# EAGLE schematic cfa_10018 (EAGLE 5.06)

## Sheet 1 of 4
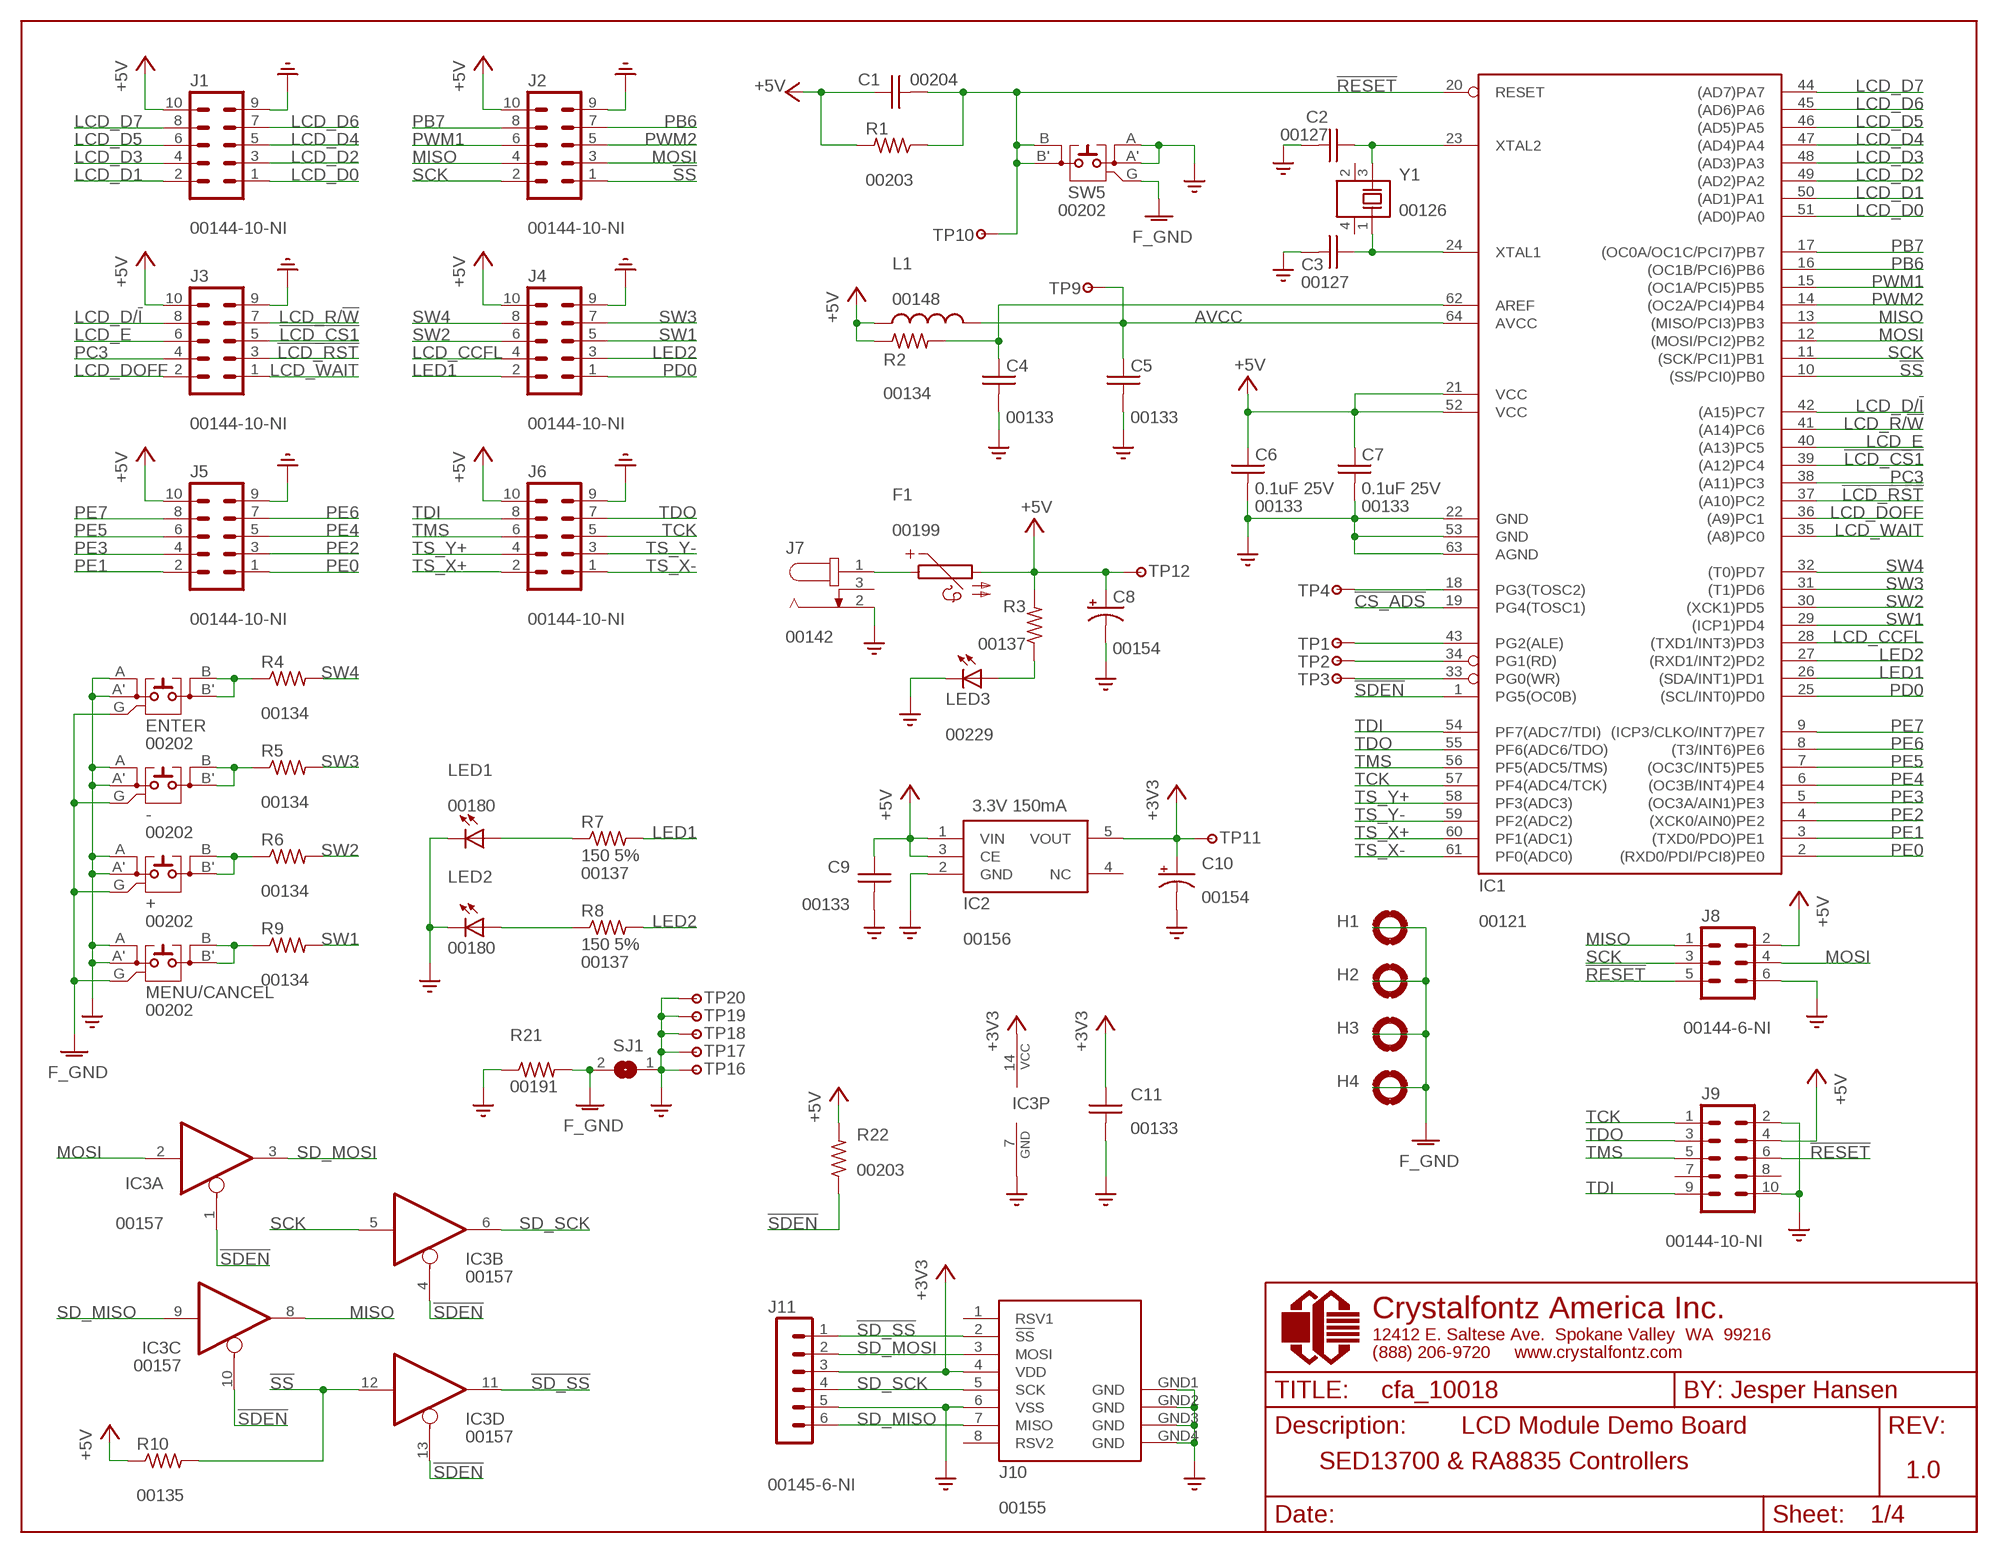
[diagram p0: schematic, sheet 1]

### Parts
+  00202  [EVQPB]
-  00202  [EVQPB]
C1  00204  [CAPC1608X90N]
C2  00127  [CAPC1608X87N]
C3  00127  [CAPC1608X87N]
C4  00133  [CAPC1608X87N]
C5  00133  [CAPC1608X87N]
C6  00133  [CAPC1608X87N]
C7  00133  [CAPC1608X87N]
C8  00154  [CAPMP6032X250N]
C9  00133  [CAPC1608X87N]
C10  00154  [CAPMP6032X250N]
C11  00133  [CAPC1608X87N]
ENTER  00202  [EVQPB]
F1  00199  [RESC3216X85N]
H1  MOUNT-PAD-ROUND3.2  [3,2-PAD]
H2  MOUNT-PAD-ROUND3.2  [3,2-PAD]
H3  MOUNT-PAD-ROUND3.2  [3,2-PAD]
H4  MOUNT-PAD-ROUND3.2  [3,2-PAD]
IC1  00121  [TQFP64-AEB]
IC2  00156  [SOT23-5L]
IC3  00157  [TSSOP14]
J1  00144-10-NI  [MA05-2]
J2  00144-10-NI  [MA05-2]
J3  00144-10-NI  [MA05-2]
J4  00144-10-NI  [MA05-2]
J5  00144-10-NI  [MA05-2]
J6  00144-10-NI  [MA05-2]
J7  00142  [PJ-102AH]
J8  00144-6-NI  [MA03-2]
J9  00144-10-NI  [MA05-2]
J10  00155  [3M_MICROSD]
J11  00145-6-NI  [MA06-1]
L1  00148  [R0805]
LED1  00180  [T776_LED_BOTTOM]
LED2  00180  [T776_LED_BOTTOM]
LED3  00229  [T776_LED_BOTTOM]
MENU/CANCEL  00202  [EVQPB]
R1  00203  [RESC1608X50N]
R2  00134  [RESC1608X38N]
R3  00137  [R0603]
R4  00134  [RESC1608X38N]
R5  00134  [RESC1608X38N]
R6  00134  [RESC1608X38N]
R7  00137  [R0603]
R8  00137  [R0603]
R9  00134  [RESC1608X38N]
R10  00135  [RESC1608X38N]
R21  00191  [RESC1608X55N]
R22  00203  [RESC1608X50N]
SJ1  SJ  [SJ]
SW5  00202  [EVQPB]
TP1  TP-VIA-3.2MM  [VIA-3.2MM-HOLE]
TP2  TP-VIA-3.2MM  [VIA-3.2MM-HOLE]
TP3  TP-VIA-3.2MM  [VIA-3.2MM-HOLE]
TP4  TP-VIA-3.2MM  [VIA-3.2MM-HOLE]
TP9  TP-VIA-1.0MM  [VIA-1MM-HOLE]
TP10  TP-VIA-1.0MM  [VIA-1MM-HOLE]
TP11  TP-VIA-1.0MM  [VIA-1MM-HOLE]
TP12  TP-VIA-1.0MM  [VIA-1MM-HOLE]
TP16  TP-VIA-1.0MM  [VIA-1MM-HOLE]
TP17  TP-VIA-1.0MM  [VIA-1MM-HOLE]
TP18  TP-VIA-1.0MM  [VIA-1MM-HOLE]
TP19  TP-VIA-1.0MM  [VIA-1MM-HOLE]
TP20  TP-VIA-1.0MM  [VIA-1MM-HOLE]
Y1  00126  [ECX-64]

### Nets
!CS_ADS: IC1.19(PG4(TOSC1)) ; also sheet 2
!LCD_CS1: IC1.39((A12)PC4) J3.5 ; also sheet 2
!LCD_RST: IC1.37((A10)PC2) J3.3 ; also sheet 2
!RESET: C1.2 IC1.20(RESET) J8.5 J9.6 R1.1 SW5.B SW5.B' TP10.1
!SD_SS: IC3.11(D:O) J10.2(!SS) J11.1
!SDEN: IC1.1(PG5(OC0B)) IC3.1(A:OE) IC3.4(B:OE) IC3.10(C:OE) IC3.13(D:OE) R22.1
!SS: IC1.10((SS/PCI0)PB0) IC3.12(D:I) J2.1 R10.2
+3V3: C10.1(+) C11.1 IC2.5(VOUT) IC3.14(P:VCC) J10.4(VDD) J11.3 TP11.1
+5V: C1.1 C6.1 C7.1 C8.1(+) C9.1 F1.2 IC1.21(VCC) IC1.52(VCC) IC2.1(VIN) IC2.3(CE) J1.10 J2.10 J3.10 J4.10 J5.10 J6.10 J8.2 J9.4 L1.1 R1.2 R2.1 R3.2 R10.1 R22.2 TP12.1 ; also sheet 2,3
AVCC: C5.1 IC1.64(AVCC) L1.2 TP9.1
FOO: +.A +.A' -.A -.A' C2.2 C3.2 C4.2 C5.2 C6.2 C7.2 C8.2(-) C9.2 C10.2(-) C11.2 ENTER.A ENTER.A' IC1.22(GND) IC1.53(GND) IC1.63(AGND) IC2.2(GND) IC3.7(P:GND) J1.9 J2.9 J3.9 J4.9 J5.9 J6.9 J7.2 J8.6 J9.2 J9.10 J10.6(VSS) J10.GND1(GND) J10.GND2(GND) J10.GND3(GND) J10.GND4(GND) J11.5 LED1.K(C) LED2.K(C) LED3.K(C) MENU/CANCEL.A MENU/CANCEL.A' R21.1 SJ1.1 SW5.A SW5.A' TP16.1 TP17.1 TP18.1 TP19.1 TP20.1 ; supply symbol labelled GND ; also sheet 2,3
GNDA: +.G -.G ENTER.G H1.B3,2(MOUNT) H2.B3,2(MOUNT) H3.B3,2(MOUNT) H4.B3,2(MOUNT) MENU/CANCEL.G R21.2 SJ1.2 SW5.G ; supply symbol labelled F_GND ; also sheet 2
LCD_CCFL: IC1.28((TXD1/INT3)PD3) J4.4 ; also sheet 3
LCD_D0: IC1.51((AD0)PA0) J1.1 ; also sheet 2
LCD_D1: IC1.50((AD1)PA1) J1.2 ; also sheet 2
LCD_D2: IC1.49((AD2)PA2) J1.3 ; also sheet 2
LCD_D3: IC1.48((AD3)PA3) J1.4 ; also sheet 2
LCD_D4: IC1.47((AD4)PA4) J1.5 ; also sheet 2
LCD_D5: IC1.46((AD5)PA5) J1.6 ; also sheet 2
LCD_D6: IC1.45((AD6)PA6) J1.7 ; also sheet 2
LCD_D7: IC1.44((AD7)PA7) J1.8 ; also sheet 2
LCD_D/!I: IC1.42((A15)PC7) J3.8 ; also sheet 2
LCD_DOFF: IC1.36((A9)PC1) J3.2 ; also sheet 2
LCD_E: IC1.40((A13)PC5) J3.6 ; also sheet 2
LCD_R/!W: IC1.41((A14)PC6) J3.7 ; also sheet 2
LCD_WAIT: IC1.35((A8)PC0) J3.1 ; also sheet 2
LED1: IC1.26((SDA/INT1)PD1) J4.2 R7.2
LED2: IC1.27((RXD1/INT2)PD2) J4.3 R8.2
MISO: IC1.13((MISO/PCI3)PB3) IC3.8(C:O) J2.4 J8.1 ; also sheet 2
MOSI: IC1.12((MOSI/PCI2)PB2) IC3.2(A:I) J2.3 J8.4 ; also sheet 2
N$1: C2.1 IC1.23(XTAL2) Y1.3
N$2: ENTER.B ENTER.B' R4.1
N$3: C3.1 IC1.24(XTAL1) Y1.1
N$4: -.B -.B' R5.1
N$6: +.B +.B' R6.1
N$7: LED1.A R7.1
N$8: MENU/CANCEL.B MENU/CANCEL.B' R9.1
N$9: C4.1 IC1.62(AREF) R2.2
N$10: LED2.A R8.1
N$11: IC1.43(PG2(ALE)) TP1.1
N$13: IC1.34(PG1(RD)) TP2.1
N$14: F1.1 J7.1
N$15: IC1.33(PG0(WR)) TP3.1
N$17: LED3.A R3.1
N$18: IC1.18(PG3(TOSC2)) TP4.1
PB6: IC1.16((OC1B/PCI6)PB6) J2.7
PB7: IC1.17((OC0A/OC1C/PCI7)PB7) J2.8
PC3: IC1.38((A11)PC3) J3.4
PD0: IC1.25((SCL/INT0)PD0) J4.1 ; also sheet 2
PE0: IC1.2((RXD0/PDI/PCI8)PE0) J5.1
PE1: IC1.3((TXD0/PDO)PE1) J5.2
PE2: IC1.4((XCK0/AIN0)PE2) J5.3
PE3: IC1.5((OC3A/AIN1)PE3) J5.4
PE4: IC1.6((OC3B/INT4)PE4) J5.5
PE5: IC1.7((OC3C/INT5)PE5) J5.6
PE6: IC1.8((T3/INT6)PE6) J5.7
PE7: IC1.9((ICP3/CLKO/INT7)PE7) J5.8
PWM1: IC1.15((OC1A/PCI5)PB5) J2.6 ; also sheet 3
PWM2: IC1.14((OC2A/PCI4)PB4) J2.5 ; also sheet 3
SCK: IC1.11((SCK/PCI1)PB1) IC3.5(B:I) J2.2 J8.3 ; also sheet 2
SD_MISO: IC3.9(C:I) J10.7(MISO) J11.6
SD_MOSI: IC3.3(A:O) J10.3(MOSI) J11.2
SD_SCK: IC3.6(B:O) J10.5(SCK) J11.4
SW1: IC1.29((ICP1)PD4) J4.5 R9.2
SW2: IC1.30((XCK1)PD5) J4.6 R6.2
SW3: IC1.31((T1)PD6) J4.7 R5.2
SW4: IC1.32((T0)PD7) J4.8 R4.2
TCK: IC1.57(PF4(ADC4/TCK)) J6.5 J9.1
TDI: IC1.54(PF7(ADC7/TDI)) J6.8 J9.9
TDO: IC1.55(PF6(ADC6/TDO)) J6.7 J9.3
TMS: IC1.56(PF5(ADC5/TMS)) J6.6 J9.5
TS_X+: IC1.60(PF1(ADC1)) J6.2 ; also sheet 2
TS_X-: IC1.61(PF0(ADC0)) J6.1 ; also sheet 2
TS_Y+: IC1.58(PF3(ADC3)) J6.4 ; also sheet 2
TS_Y-: IC1.59(PF2(ADC2)) J6.3 ; also sheet 2
Unconnected: IC2.4(NC) J7.3 J9.7 J9.8 J10.1(RSV1) J10.8(RSV2) Y1.2 Y1.4

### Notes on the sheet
- 3.3V 150mA
- LCD Module Demo Board
- SED13700 & RA8835 Controllers
- 1.0

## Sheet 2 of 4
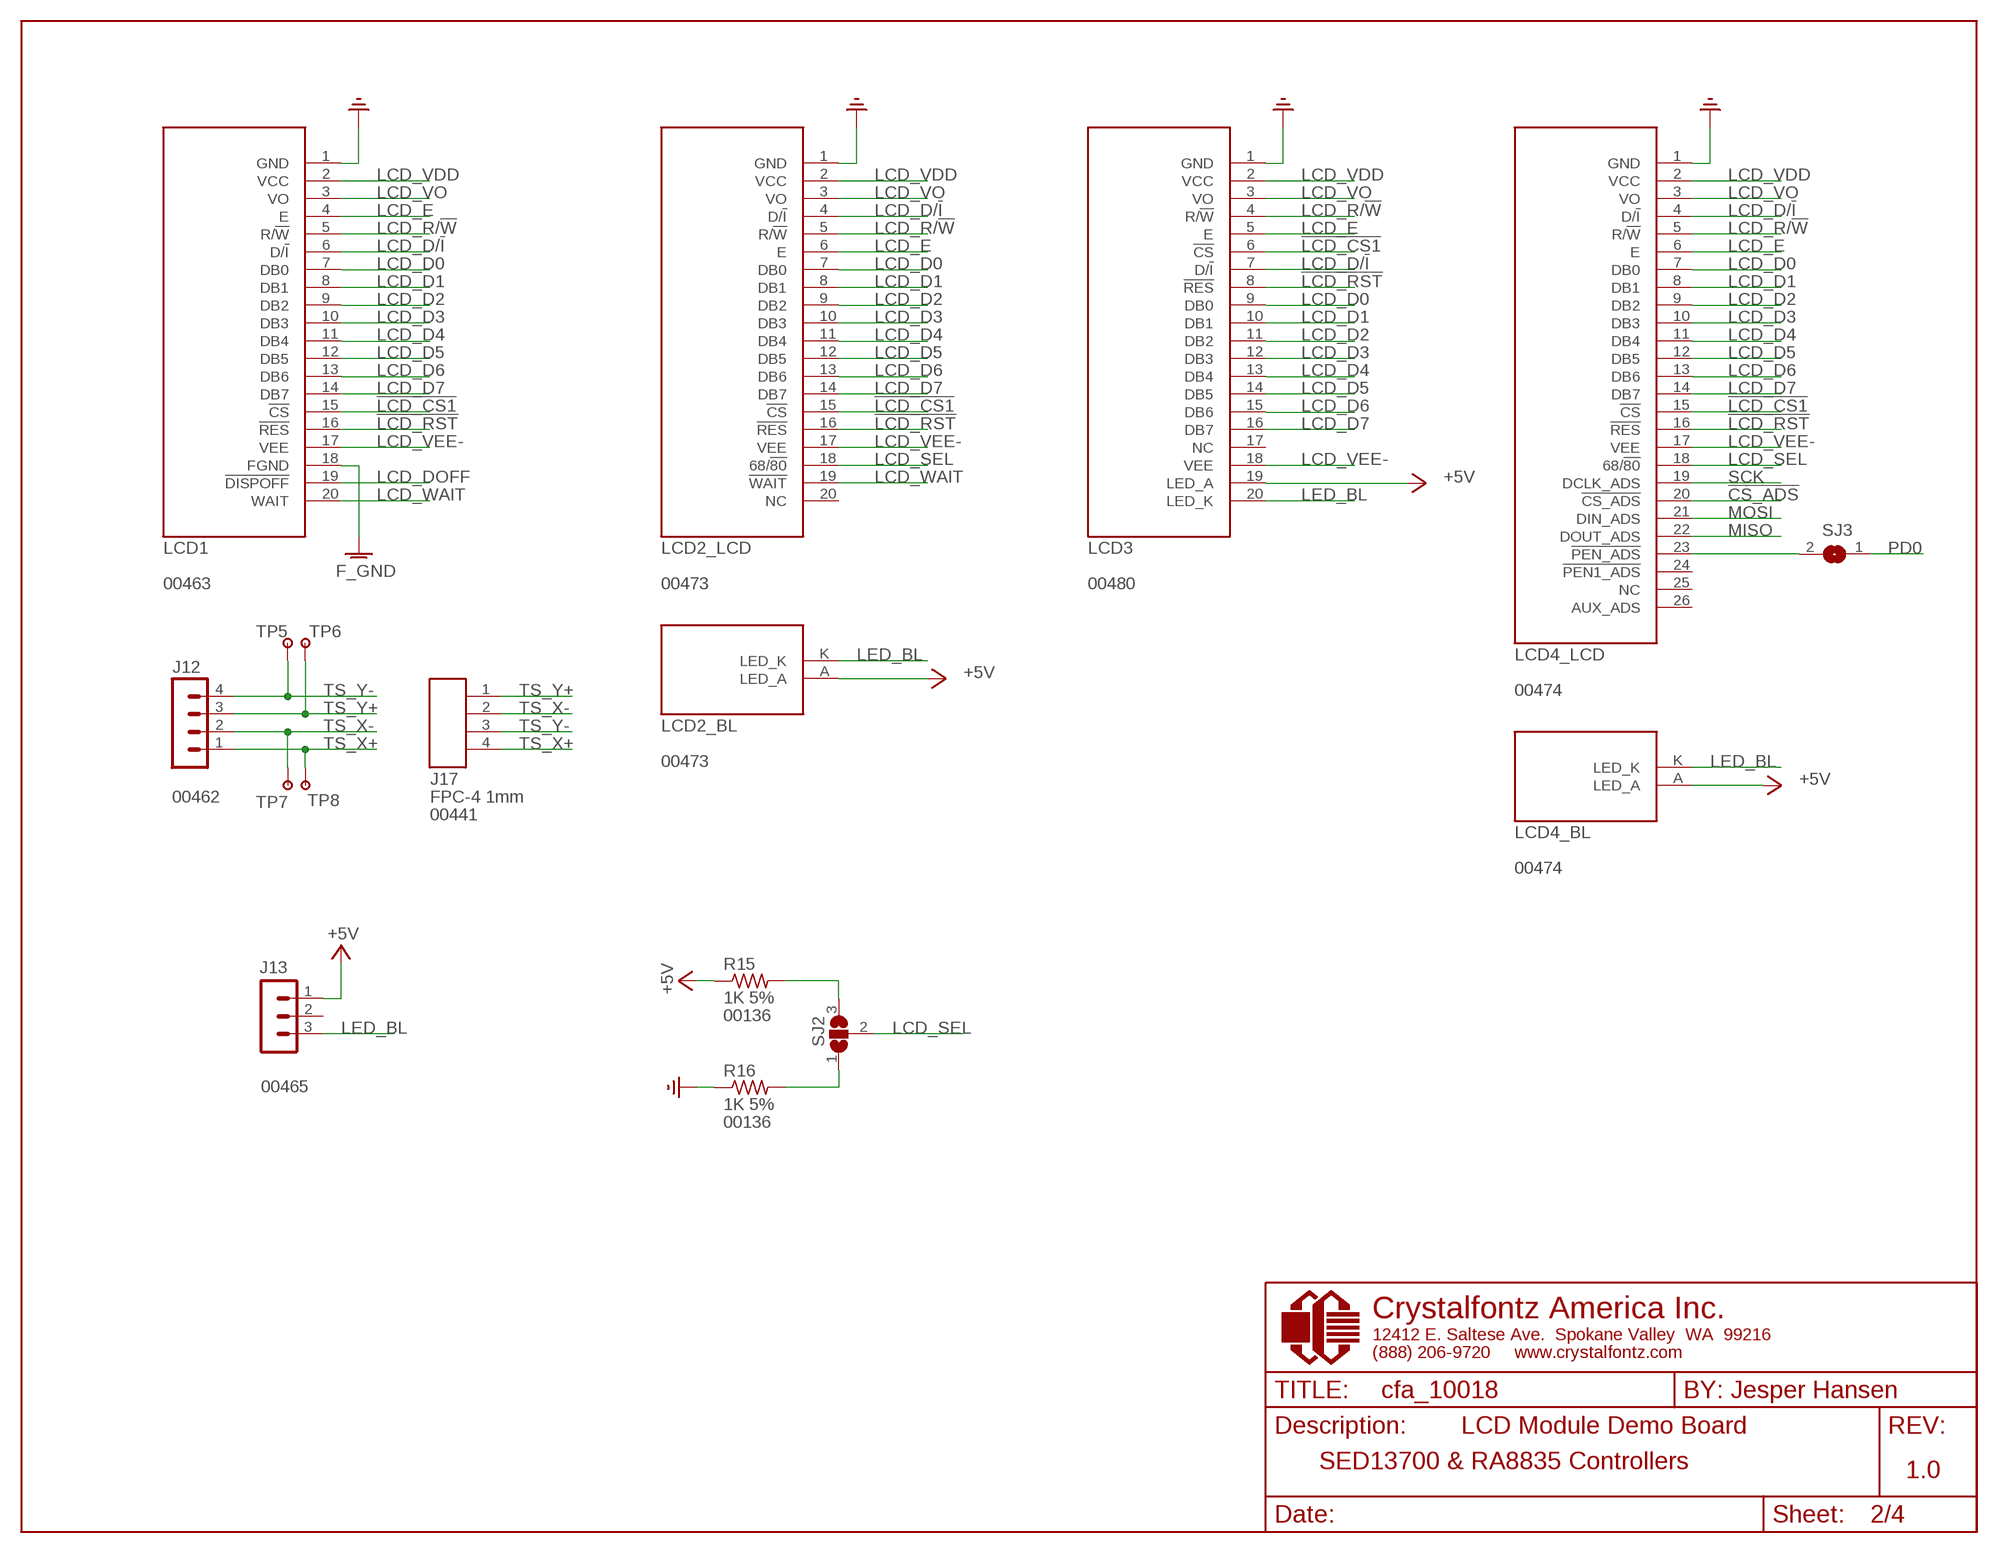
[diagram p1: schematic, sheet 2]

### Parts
J12  00462  [MA04-1W]
J13  00465  [JST_XHP3]
J17  00441  [52207-0485]
LCD1  00463  [CFAG320240_148_120]
LCD2  00473  [CFAG320240K]
LCD3  00480  [CFAG320240O]
LCD4  00474  [CFAG320240BP3]
R15  00136  [R0603]
R16  00136  [R0603]
SJ2  SJ2W  [SJ_2]
SJ3  SJ  [SJ]
TP5  TP-VIA-1.0MM  [VIA-1MM-HOLE]
TP6  TP-VIA-1.0MM  [VIA-1MM-HOLE]
TP7  TP-VIA-1.0MM  [VIA-1MM-HOLE]
TP8  TP-VIA-1.0MM  [VIA-1MM-HOLE]

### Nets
!CS_ADS: LCD4.20(_LCD:!CS_ADS) ; also sheet 1
!LCD_CS1: LCD1.15(!CS) LCD2.15(_LCD:!CS) LCD3.6(!CS) LCD4.15(_LCD:!CS) ; also sheet 1
!LCD_RST: LCD1.16(!RES) LCD2.16(_LCD:!RES) LCD3.8(!RES) LCD4.16(_LCD:!RES) ; also sheet 1
+5V: J13.1 LCD2.A(_BL:LED_A) LCD3.19(LED_A) LCD4.A(_BL:LED_A) R15.1 ; also sheet 1,3
FOO: LCD1.1(GND) LCD2.1(_LCD:GND) LCD4.1(_LCD:GND) R16.1 ; supply symbol labelled GND ; also sheet 1,3
GND: LCD3.1(GND)
GNDA: LCD1.18(FGND) ; supply symbol labelled F_GND ; also sheet 1
LCD_D0: LCD1.7(DB0) LCD2.7(_LCD:DB0) LCD3.9(DB0) LCD4.7(_LCD:DB0) ; also sheet 1
LCD_D1: LCD1.8(DB1) LCD2.8(_LCD:DB1) LCD3.10(DB1) LCD4.8(_LCD:DB1) ; also sheet 1
LCD_D2: LCD1.9(DB2) LCD2.9(_LCD:DB2) LCD3.11(DB2) LCD4.9(_LCD:DB2) ; also sheet 1
LCD_D3: LCD1.10(DB3) LCD2.10(_LCD:DB3) LCD3.12(DB3) LCD4.10(_LCD:DB3) ; also sheet 1
LCD_D4: LCD1.11(DB4) LCD2.11(_LCD:DB4) LCD3.13(DB4) LCD4.11(_LCD:DB4) ; also sheet 1
LCD_D5: LCD1.12(DB5) LCD2.12(_LCD:DB5) LCD3.14(DB5) LCD4.12(_LCD:DB5) ; also sheet 1
LCD_D6: LCD1.13(DB6) LCD2.13(_LCD:DB6) LCD3.15(DB6) LCD4.13(_LCD:DB6) ; also sheet 1
LCD_D7: LCD1.14(DB7) LCD2.14(_LCD:DB7) LCD3.16(DB7) LCD4.14(_LCD:DB7) ; also sheet 1
LCD_D/!I: LCD1.6(D/!I) LCD2.4(_LCD:D/!I) LCD3.7(D/!I) LCD4.4(_LCD:D/!I) ; also sheet 1
LCD_DOFF: LCD1.19(!DISPOFF) ; also sheet 1
LCD_E: LCD1.4(E) LCD2.6(_LCD:E) LCD3.5(E) LCD4.6(_LCD:E) ; also sheet 1
LCD_R/!W: LCD1.5(R/!W) LCD2.5(_LCD:R/!W) LCD3.4(R/!W) LCD4.5(_LCD:R/!W) ; also sheet 1
LCD_SEL: LCD2.18(_LCD:68/!80) LCD4.18(_LCD:68/!80) SJ2.2
LCD_VDD: LCD1.2(VCC) LCD2.2(_LCD:VCC) LCD3.2(VCC) LCD4.2(_LCD:VCC) ; also sheet 3
LCD_VEE-: LCD1.17(VEE) LCD2.17(_LCD:VEE) LCD3.18(VEE) LCD4.17(_LCD:VEE) ; also sheet 3
LCD_VO: LCD1.3(VO) LCD2.3(_LCD:VO) LCD3.3(VO) LCD4.3(_LCD:VO) ; also sheet 3
LCD_WAIT: LCD1.20(WAIT) LCD2.19(_LCD:!WAIT) ; also sheet 1
LED_BL: J13.3 LCD2.K(_BL:LED_K) LCD3.20(LED_K) LCD4.K(_BL:LED_K) ; also sheet 3
MISO: LCD4.22(_LCD:DOUT_ADS) ; also sheet 1
MOSI: LCD4.21(_LCD:DIN_ADS) ; also sheet 1
N$5: LCD4.23(_LCD:!PEN_ADS) SJ3.2
N$33: R15.2 SJ2.3
N$34: R16.2 SJ2.1
PD0: SJ3.1 ; also sheet 1
SCK: LCD4.19(_LCD:DCLK_ADS) ; also sheet 1
TS_X+: J12.1 J17.4 TP8.1 ; also sheet 1
TS_X-: J12.2 J17.2 TP7.1 ; also sheet 1
TS_Y+: J12.3 J17.1 TP6.1 ; also sheet 1
TS_Y-: J12.4 J17.3 TP5.1 ; also sheet 1
Unconnected: J13.2 LCD2.20(_LCD:NC) LCD3.17(NC) LCD4.24(_LCD:!PEN1_ADS) LCD4.25(_LCD:NC) LCD4.26(_LCD:AUX_ADS)

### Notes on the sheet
- LCD Module Demo Board
- SED13700 & RA8835 Controllers
- 1.0

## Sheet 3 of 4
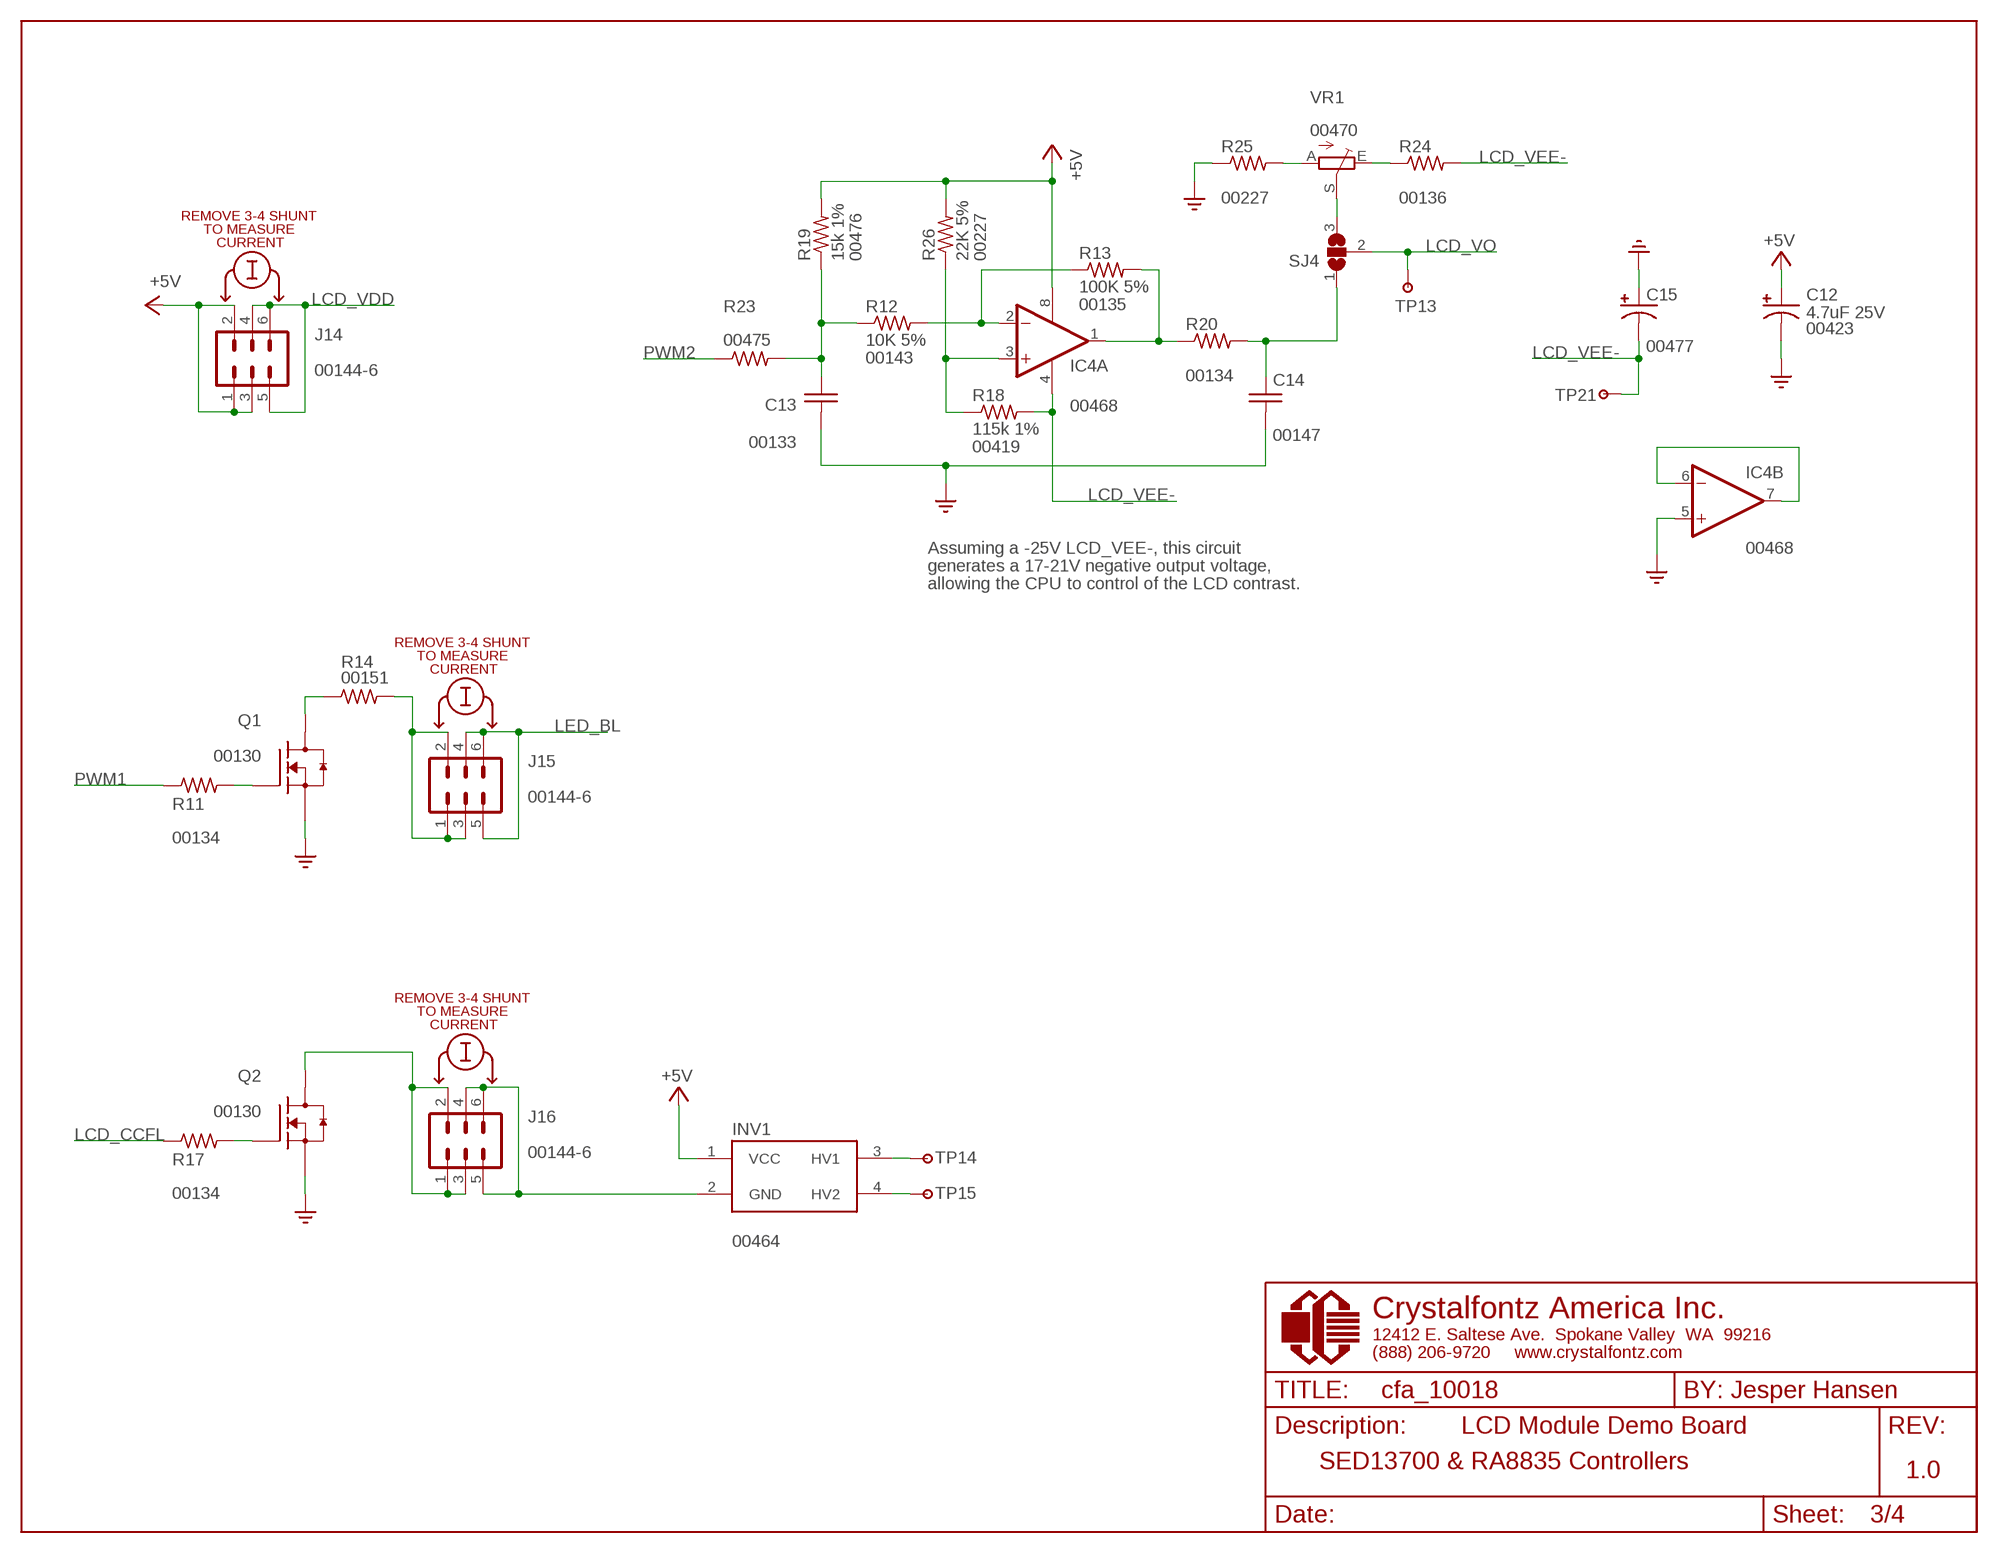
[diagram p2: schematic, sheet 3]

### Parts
C12  00423  [CT3216]
C13  00133  [CAPC1608X87N]
C14  00147  [CAPC1608X87N]
C15  00477  [CAPMP6032X250N]
IC4  00468  [SO08]
INV1  00464  [CFAICCFL1]
J14  00144-6  [MA03-2]
J15  00144-6  [MA03-2]
J16  00144-6  [MA03-2]
Q1  00130  [SOT23]
Q2  00130  [SOT23]
R11  00134  [RESC1608X38N]
R12  00143  [RESC1608X38N]
R13  00135  [RESC1608X38N]
R14  00151  [R2010]
R17  00134  [RESC1608X38N]
R18  00419  [RESC1608X55N]
R19  00476  [RESC1608X55N]
R20  00134  [RESC1608X38N]
R23  00475  [RESC1608X55N]
R24  00136  [R0603]
R25  00227  [RESC1608X38N]
R26  00227  [RESC1608X38N]
SJ4  SJ2W  [SJ_2]
TP13  TP-VIA-1.0MM  [VIA-1MM-HOLE]
TP14  TP-VIA-1.0MM  [VIA-1MM-HOLE]
TP15  TP-VIA-1.0MM  [VIA-1MM-HOLE]
TP21  TP-VIA-1.0MM  [VIA-1MM-HOLE]
VR1  00470  [S63P]

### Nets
+5V: C12.+ IC4.8(A:V+) INV1.1(VCC) J14.1 J14.2 J14.3 R19.2 R26.2 ; also sheet 1,2
FOO: C12.- C13.2 C14.2 C15.1(+) IC4.5(B:+IN) Q1.2(S) Q2.2(S) R25.1 ; supply symbol labelled GND ; also sheet 1,2
LCD_CCFL: R17.1 ; also sheet 1
LCD_VDD: J14.4 J14.5 J14.6 ; also sheet 2
LCD_VEE-: C15.2(-) IC4.4(A:V-) R18.2 R24.2 TP21.1 ; also sheet 2
LCD_VO: SJ4.2 TP13.1 ; also sheet 2
LED_BL: J15.4 J15.5 J15.6 ; also sheet 2
N$12: INV1.3(HV1) TP14.1
N$16: INV1.4(HV2) TP15.1
N$19: IC4.2(A:-IN) R12.2 R13.1
N$20: IC4.1(A:OUT) R13.2 R20.1
N$22: C14.1 R20.2 SJ4.1
N$25: J15.1 J15.2 J15.3 R14.2
N$27: IC4.3(A:+IN) R18.1 R26.1
N$30: Q1.3(D) R14.1
N$31: Q1.1(G) R11.2
N$35: C13.1 R12.1 R19.1 R23.2
N$36: IC4.6(B:-IN) IC4.7(B:OUT)
N$37: J16.1 J16.2 J16.3 Q2.3(D)
N$38: INV1.2(GND) J16.4 J16.5 J16.6
N$39: SJ4.3 VR1.S
N$40: Q2.1(G) R17.2
N$41: R25.2 VR1.A
N$42: R24.1 VR1.E
PWM1: R11.1 ; also sheet 1
PWM2: R23.1 ; also sheet 1

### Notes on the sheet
- REMOVE 3-4 SHUNT
- TO MEASURE
- CURRENT
- Assuming a -25V LCD_VEE-, this circuit
- generates a 17-21V negative output voltage,
- allowing the CPU to control of the LCD contrast.
- REMOVE 3-4 SHUNT
- TO MEASURE
- CURRENT
- REMOVE 3-4 SHUNT
- TO MEASURE
- CURRENT
- LCD Module Demo Board
- SED13700 & RA8835 Controllers
- 1.0

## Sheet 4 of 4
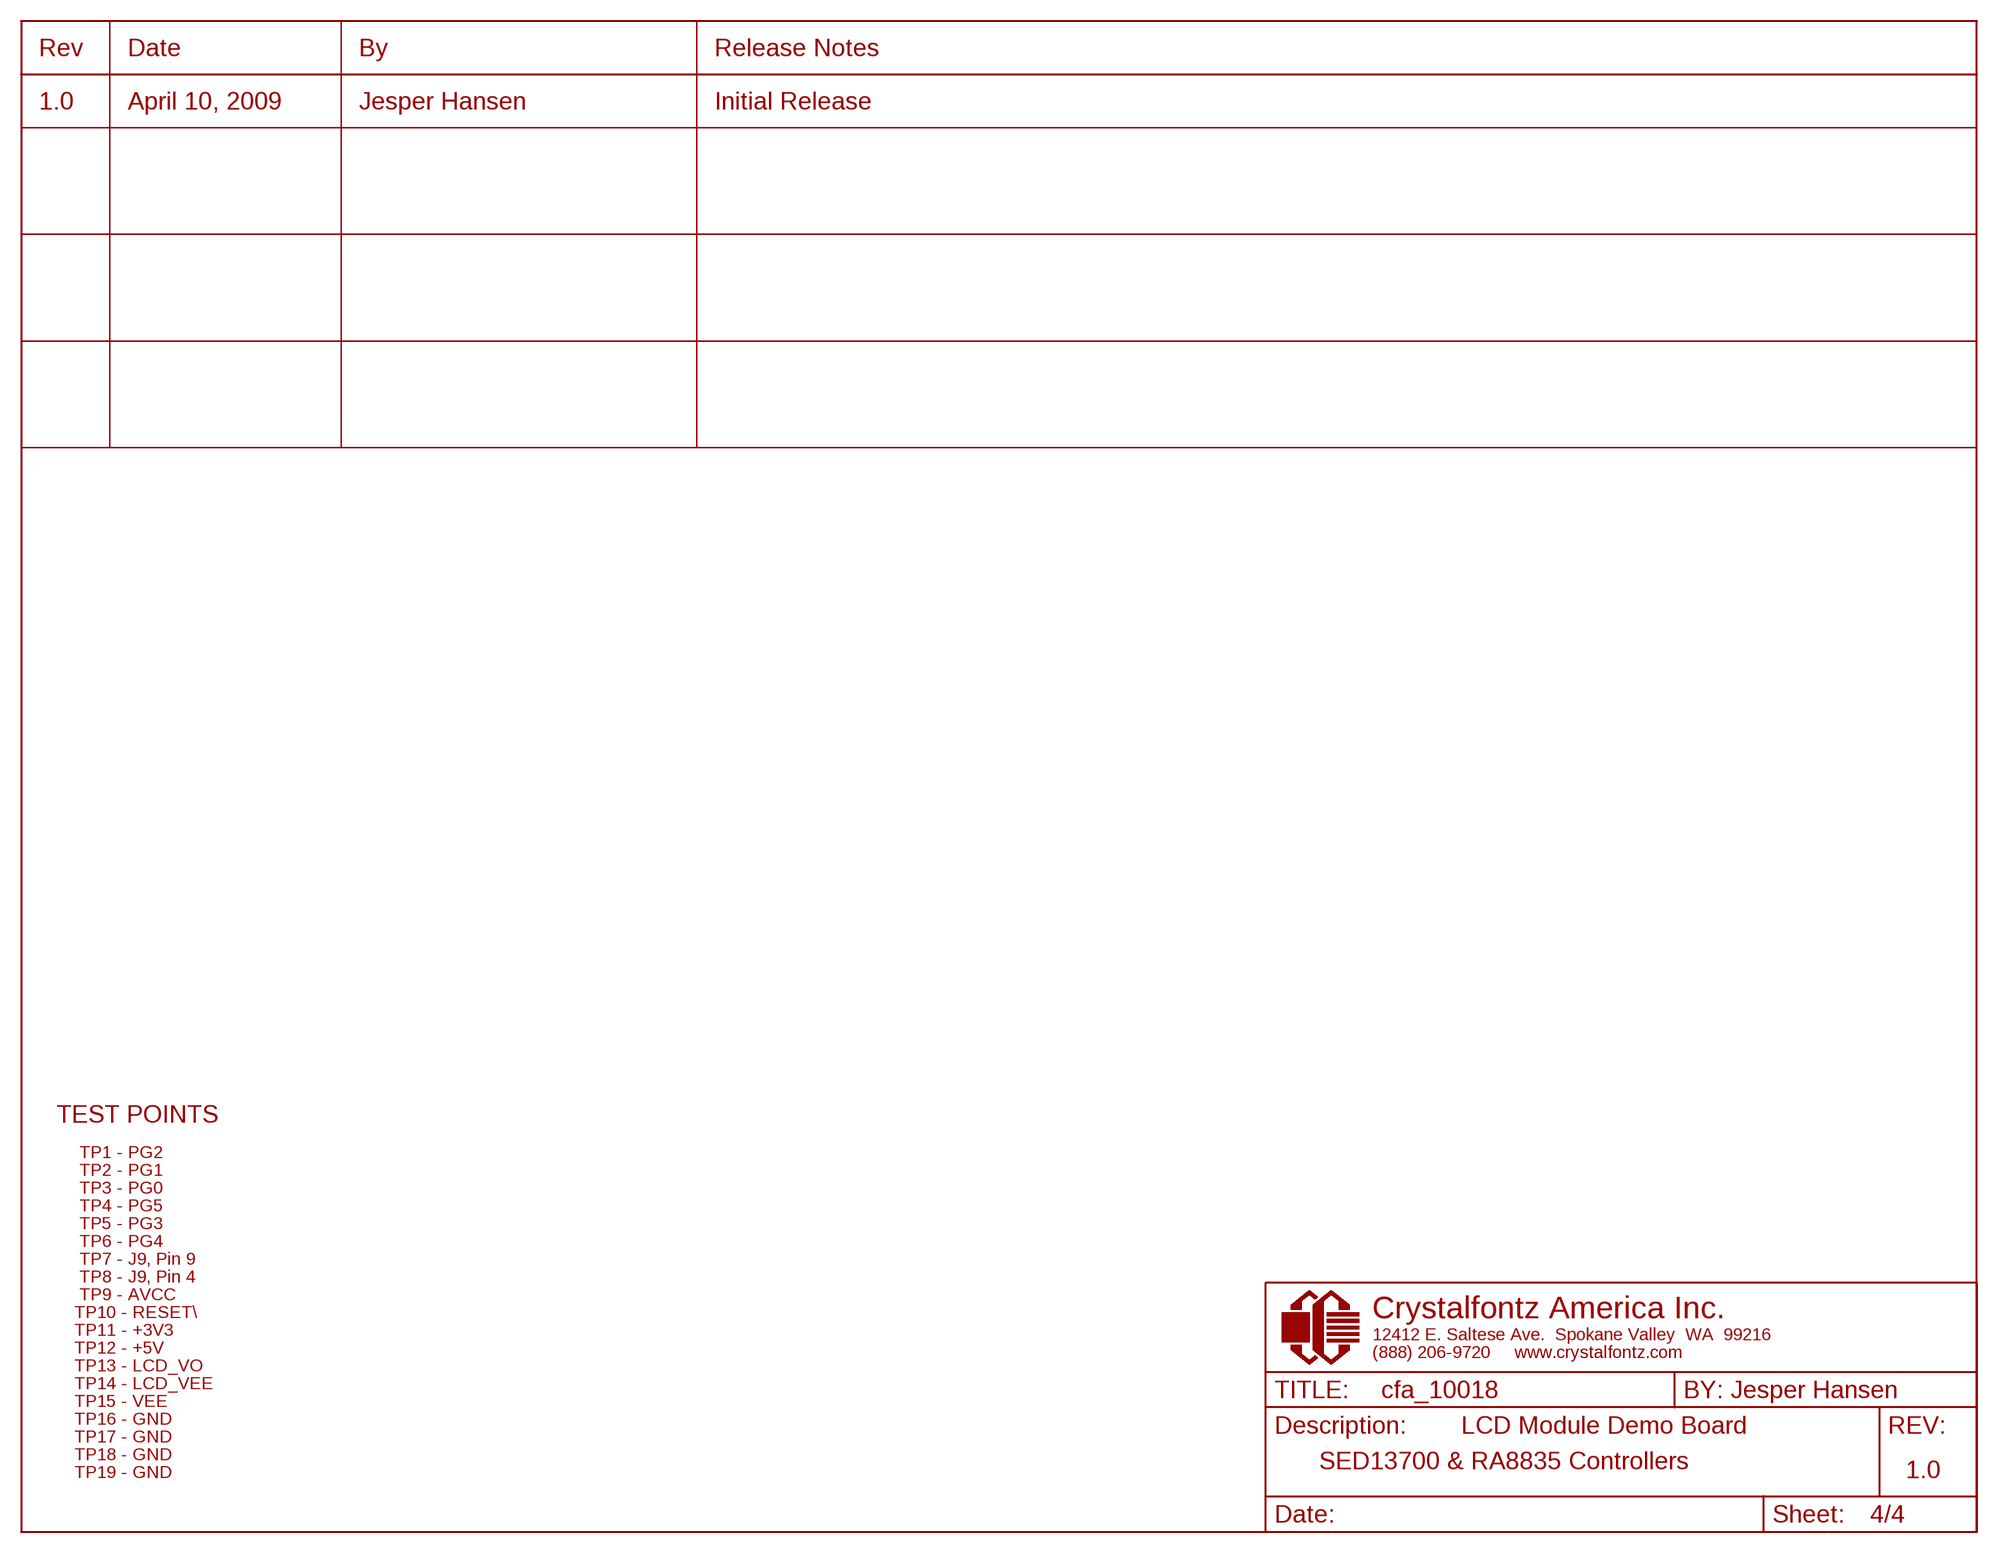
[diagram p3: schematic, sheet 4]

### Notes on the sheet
- Rev | Date | By | Release Notes
- 1.0 | April 10, 2009 | Jesper Hansen | Initial Release
- TEST POINTS
- TP1 - PG2
- TP2 - PG1
- TP3 - PG0
- TP4 - PG5
- TP5 - PG3
- TP6 - PG4
- TP7 - J9, Pin 9
- TP8 - J9, Pin 4
- TP9 - AVCC
- TP10 - RESET\\
- TP11 - +3V3
- TP12 - +5V
- TP13 - LCD_VO
- TP14 - LCD_VEE
- TP15 - VEE
- TP16 - GND
- LCD Module Demo Board
- TP17 - GND
- TP18 - GND
- SED13700 & RA8835 Controllers
- TP19 - GND | 1.0

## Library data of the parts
+ - ENTER MENU/CANCEL SW5 = proddev_lib:00202: SPST MOM W/GND, 6MM LIGHT TOUCH SW W/GND H=7 TH; DESC: SPST MOM W/GND
C1 = proddev_lib:00204: 0.22uF 10V, CAP .22UF 10V CERAMIC X5R 0603; DESC: 0.22uF 10V
C2 C3 = proddev_lib:00127: 20pF, CAP CER 20PF 50V 5% C0G 0603; DESC: 20pF
C4-C7 C9 C11 C13 = proddev_lib:00133: 0.1uF 25V, CAP .1UF 25V CERAMIC X7R 0603; DESC: 0.1uF 25V
C8 C10 = proddev_lib:00154: 10uF 10V, CAP TANT 10UF 10V 10% LOESR SMD; DESC: 10uF 10V
C12 = proddev_lib2:00423: 4.7UF 25V, CAP TANT 4.7UF 25V 20% SMD SIZE 3216; DESC: 4.7uF 25V
C14 = proddev_lib:00147: 1.0uF 10V, CAP CERAMIC 1UF 10V X5R 0603; DESC: 1.0uF 10V
C15 = proddev_lib2:00477: 10uF 35V,CAP TANTALUM 10UF 35V 20% SMD; DESC: 10uF 35V
F1 = proddev_lib:00199: 500mA, PTC RESETTABLE .50A 13.2V 1206; DESC: 500mA PTC
H1-H4 = holes:MOUNT-PAD-ROUND: MOUNTING PAD, round
IC1 = proddev_lib:00121: ATmega2561-16AU, IC AVR MCU 256K 16MHZ 64TQFP 256 Kbytes FLASH 8 Kbytes SRAM 4 Kbytes EEPROM DUAL USART 8-channel 10 bit ADC; DESC: ATmega2561-16AU
IC2 = proddev_lib:00156: MC78PC33, IC REG LDO 150MA 3.3V LN SOT23-5; DESC: MC78PC33
IC3 = proddev_lib:00157: SN74CB3T3125, IC 3.3V QUAD FET SWITCH 14TSSOP; DESC: SN74CB3T3125
IC4 = proddev_lib2:00468: LT1490 Dual/Quad Over-The-Top Micropower Rail-to-Rail Input and Output Op Amps; DESC: LT1490
INV1 = proddev_lib2:00464: CCFL Inverter +5V input 280Vrms output Input Power 2.5W (nom @5V) Tube current 5.7 mA Operating frequency 35 kHz; DESC: CFAICCFL1
J1-J6 J9 = proddev_lib:00144-10-NI: 2X5 HDR, CONN HDR BRKWAY .100 VERT; DESC: 2X5 HDR
J7 = proddev_lib:00142: 2.1x5.5MM, CONN PWR JACK 2.1X5.5MM HIGH CUR; DESC: 2.1x5.5MM
J8 = proddev_lib:00144-6-NI: 2X3 HDR, CONN HDR BRKWAY .100 VERT; DESC: 2X3 HDR
J10 = proddev_lib:00155: MICROSD SOCKET, CONN EJECT MICROSD PUSH-PUSH SMD; DESC: MICROSD SOCKET
J11 = proddev_lib:00145-6-NI: 1X6 HDR, CONN HDR BRKWAY .100 VERT; DESC: 1X6 HDR
J12 = proddev_lib2:00462: 4-pin 0.1" connector, right-angle; DESC: 1x4 HDR
J13 = proddev_lib2:00465: CONN HEADER XH TOP 3POS 2.5MM JST XHP3 connector; DESC: JST XHP3
J14-J16 = proddev_lib:00144-6: 2X3 HDR, CONN HDR BRKWAY .100 VERT; DESC: 2X3 HDR
J17 = proddev_lib2:00441: CONN FFC/FPC 4POS 1MM R/A SMD, TOP CONTACTS; DESC: FPC-4 1mm
L1 = proddev_lib:00148: 10uH, FERRITE CHIP 1000 OHM 200MA 0805; DESC: 10uH FC
LCD1 = proddev_lib2:00463: Crystalfontz CFAG320240CX series Size 148 x 120 mm Also can be used with the CFAG320240C0 displays; DESC: CFAG320240CX
LCD2 = proddev_lib2:00473: Crystalfontz CFAG320240K series Size 142 x 96 mm; DESC: CFAG320240K
LCD3 = proddev_lib2:00480: Crystalfontz CFAG320240O series Size 139 x 100 mm; DESC: CFAG320240O
LCD4 = proddev_lib2:00474: Crystalfontz CFAG320240BP3 series Size 160 x 109 mm; DESC: CFAG320240BP3
LED1 LED2 = proddev_lib:00180: LST776, LED SUP RED REV GULWNG 645NM SMD; DESC: LST776 RED
LED3 = proddev_lib:00229: LED GRN, LED PURE GRN REV GLWNG 562NM SMD; DESC: LED GRN REV
Q1 Q2 = proddev_lib:00130: IRLML2402, MOSFET N-CH 20V 1.2A SOT-23; DESC: IRLML2402
R1 R22 = proddev_lib:00203: 47K 1/10W 5%, RES 47K OHM 1/10W 5% 0603 SMD; DESC: 47K 5%
R2 R4-R6 R9 R11 R17 R20 = proddev_lib:00134: 100, RES 100 OHM 1/10W 5% 0603 SMD; DESC: 100
R3 R7 R8 = proddev_lib:00137: 150, RES 150 OHM 1/10W 5% 0603 SMD; DESC: 150 5%
R10 R13 = proddev_lib:00135: 100K, RES 100K OHM 1/10W 5% 0603 SMD; DESC: 100K 5%
R12 = proddev_lib:00143: 10K, RES 10K OHM 1/10W 5% 0603 SMD; DESC: 10K 5%
R14 = proddev_lib:00151: R 1/2W 2010, BACKLIGHT RES 1/2W 2010 SMD; DESC: R 1/2W 2010
R15 R16 R24 = proddev_lib:00136: 1K, RES 1.0K OHM 1/10W 5% 0603 SMD; DESC: 1K 5%
R18 = proddev_lib2:00419: 115K 1/10W 1%, RES 115K OHM 1/10W 1% 0603 SMD; DESC: 115k 1%
R19 = proddev_lib2:00476: 15.0K 1/10W 1%,RES 15.0K OHM 1/10W 1% 0603 SMD; DESC: 15k 1%
R21 = proddev_lib:00191: 1.0M 1/10W 1%, RES 1.00M OHM 1/10W 1% 0603 SMD; DESC: 1.0M 1%
R23 = proddev_lib2:00475: 68.0K 1/10W 1%,RES 68.0K OHM 1/10W 1% 0603 SMD; DESC: 68k 1%
R25 R26 = proddev_lib:00227: 22K, RES 22K OHM 1/10W 5% 0603 SMD; DESC: 22K 5%
SJ1 SJ3 = proddev_lib:SJ: SMD solder JUMPER
SJ2 SJ4 = proddev_lib:SJ2W: SMD solder JUMPER
TP1-TP4 = proddev_lib:TP-VIA-3.2MM: 3.2MM Hole Via TP
TP5-TP21 = proddev_lib:TP-VIA-1.0MM: TP 1MM HOLE
VR1 = proddev_lib2:00470: Single Turn Trimmer 3/8 SQ 10Kohms 10% Cermet; DESC: 10k 10%
Y1 = proddev_lib:00126: 16MHz, CRYSTAL 16.000MHZ SMT 20PF; DESC: 16MHz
